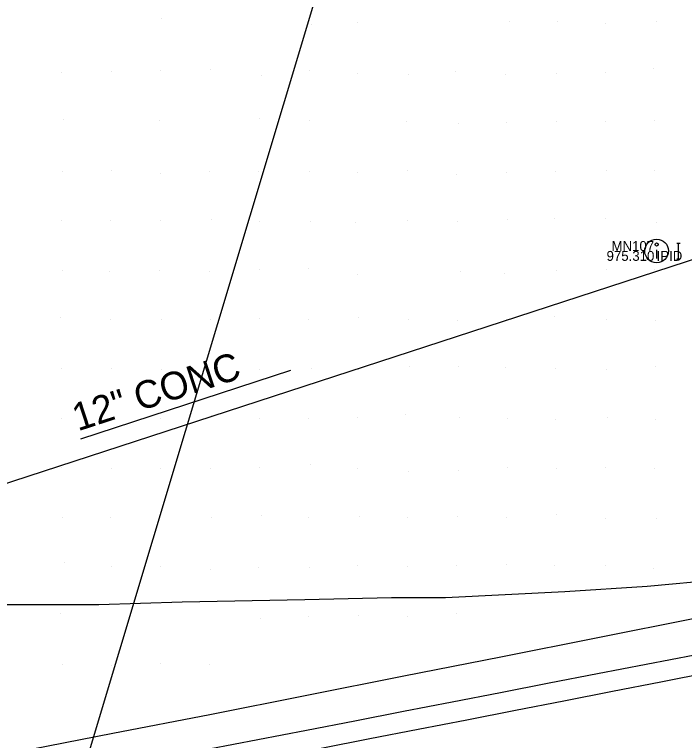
# Model space of a CAD drawing. Extents: x 2262025 to 2264532, y 740981 to 742724.
# Drawn here: x 2263020.8 to 2263088.6, y 742043.1 to 742116.6 of the extents above; entities that cross this region are included whole.
import ezdxf

# ---------------------------------------------------------------- set-up
doc = ezdxf.new("R2010")
doc.units = 0
for name, color, linetype in [('DR_X_Storm_Sewer', 7, 'Continuous'), ('DR_X_Text', 7, 'Continuous'), ('GE_X_Alignment_1000_Curve_Data', 7, 'Continuous'), ('GE_X_Alignment_100_Cardinal_Points', 7, 'Continuous'), ('GE_X_Alignment_100_Curve_Data', 7, 'Continuous'), ('Ground Shots', 7, 'Continuous'), ('HY_X_Spring_Cells', 7, 'Continuous'), ('RW_X_CL', 7, 'Continuous'), ('RW_X_CL_1000_Distances', 7, 'Continuous'), ('SV_X_Text_Comment', 7, 'Continuous'), ('SV_X_Text_Elevation', 7, 'Continuous')]:
    doc.layers.add(name, color=color, linetype=linetype)

msp = doc.modelspace()

# ---------------------------------------------------------------- linework, layer by layer
at = {"layer": 'DR_X_Storm_Sewer'}
for p, q in [((2263148.873, 742443.512), (2262984.252, 741895.043)), ((2263148.873, 742443.512), (2262984.252, 741895.043)), ((2262955.205, 742048.032), (2263118.436, 742101.27))]:
    msp.add_line(p, q, dxfattribs=at)
at = {"layer": 'DR_X_Text'}
msp.add_line((2263048.755, 742080.542), (2263027.511, 742073.613), dxfattribs=at)
at = {"layer": 'GE_X_Alignment_1000_Curve_Data'}
msp.add_lwpolyline([(2263040.535, 742042.275), (2263045.444, 742043.228), (2263050.352, 742044.182), (2263055.26, 742045.135), (2263060.168, 742046.088), (2263065.077, 742047.041), (2263069.985, 742047.994), (2263074.893, 742048.947), (2263079.802, 742049.9), (2263084.71, 742050.853), (2263089.618, 742051.806)], dxfattribs=at)
at = {"layer": 'GE_X_Alignment_100_Cardinal_Points'}
msp.add_lwpolyline([(2263009.27, 742056.896), (2263029.372, 742056.896), (2263037.795, 742057.158), (2263050.186, 742057.378), (2263058.962, 742057.599), (2263064.408, 742057.599), (2263076.491, 742058.195), (2263084.803, 742058.746), (2263099.443, 742060.092), (2263108.285, 742061.151), (2263115.958, 742062.254), (2263129.143, 742064.35), (2263140.41, 742066.38), (2263153.243, 742069.027), (2263159.461, 742070.241)], dxfattribs=at)
at = {"layer": 'GE_X_Alignment_100_Curve_Data'}
msp.add_lwpolyline([(2263020.956, 742041.954), (2263030.773, 742043.857), (2263040.591, 742045.759), (2263050.4, 742047.704), (2263060.208, 742049.654), (2263070.016, 742051.604), (2263079.824, 742053.554), (2263089.632, 742055.504), (2263099.437, 742057.471), (2263109.235, 742059.471), (2263119.032, 742061.472), (2263128.831, 742063.468), (2263138.595, 742065.612), (2263148.411, 742067.469), (2263158.09, 742069.913), (2263167.942, 742071.492), (2263177.746, 742073.459), (2263187.567, 742075.344), (2263197.385, 742077.239), (2263207.198, 742079.166), (2263217.01, 742081.093), (2263226.822, 742083.024), (2263236.633, 742084.961)], dxfattribs=at)
at = {"layer": 'Ground Shots'}
for p, q in [((2263035.649, 742116.116), (2263035.649, 742116.116)), ((2263050.869, 742115.572), (2263050.869, 742115.572)), ((2263055.569, 742115.764), (2263055.569, 742115.764)), ((2263070.887, 742115.817), (2263070.887, 742115.817)), ((2263075.773, 742115.86), (2263075.773, 742115.86)), ((2263080.613, 742115.663), (2263080.613, 742115.663)), ((2263085.782, 742115.871), (2263085.782, 742115.871)), ((2263025.591, 742110.658), (2263025.591, 742110.658)), ((2263030.687, 742110.796), (2263030.687, 742110.796)), ((2263035.604, 742110.941), (2263035.604, 742110.941)), ((2263040.656, 742111.047), (2263040.656, 742111.047)), ((2263050.621, 742110.87), (2263050.621, 742110.87)), ((2263055.569, 742110.592), (2263055.569, 742110.592)), ((2263060.715, 742110.464), (2263060.715, 742110.464)), ((2263065.441, 742110.842), (2263065.441, 742110.842)), ((2263070.499, 742110.515), (2263070.499, 742110.515)), ((2263075.67, 742110.625), (2263075.67, 742110.625)), ((2263080.639, 742110.688), (2263080.639, 742110.688)), ((2263085.423, 742111.086), (2263085.423, 742111.086)), ((2263045.781, 742110.358), (2263045.781, 742110.358)), ((2263045.641, 742106.023), (2263045.641, 742106.023)), ((2263025.785, 742105.931), (2263025.785, 742105.931)), ((2263035.515, 742105.822), (2263035.515, 742105.822)), ((2263050.635, 742105.834), (2263050.635, 742105.834)), ((2263060.454, 742105.733), (2263060.454, 742105.733)), ((2263065.761, 742105.547), (2263065.761, 742105.547)), ((2263070.553, 742105.673), (2263070.553, 742105.673)), ((2263075.597, 742105.755), (2263075.597, 742105.755)), ((2263080.606, 742105.701), (2263080.606, 742105.701)), ((2263085.537, 742105.858), (2263085.537, 742105.858)), ((2263025.696, 742100.697), (2263025.696, 742100.697)), ((2263030.599, 742100.763), (2263030.599, 742100.763)), ((2263035.589, 742100.493), (2263035.589, 742100.493)), ((2263040.594, 742100.696), (2263040.594, 742100.696)), ((2263045.533, 742100.7), (2263045.533, 742100.7)), ((2263050.615, 742100.673), (2263050.615, 742100.673)), ((2263055.543, 742100.608), (2263055.543, 742100.608)), ((2263060.573, 742100.758), (2263060.573, 742100.758)), ((2263065.545, 742100.42), (2263065.545, 742100.42)), ((2263070.63, 742100.543), (2263070.63, 742100.543)), ((2263075.511, 742100.671), (2263075.511, 742100.671)), ((2263080.722, 742100.777), (2263080.722, 742100.777)), ((2263085.58, 742100.83), (2263085.58, 742100.83)), ((2263030.58, 742095.745), (2263030.58, 742095.745)), ((2263040.777, 742095.822), (2263040.777, 742095.822)), ((2263060.553, 742095.764), (2263060.553, 742095.764)), ((2263070.643, 742095.843), (2263070.643, 742095.843)), ((2263075.447, 742095.896), (2263075.447, 742095.896)), ((2263080.601, 742095.918), (2263080.601, 742095.918)), ((2263025.63, 742095.695), (2263025.63, 742095.695)), ((2263035.624, 742095.682), (2263035.624, 742095.682)), ((2263045.623, 742095.611), (2263045.623, 742095.611)), ((2263050.757, 742095.613), (2263050.757, 742095.613)), ((2263055.33, 742095.509), (2263055.33, 742095.509)), ((2263065.659, 742095.584), (2263065.659, 742095.584)), ((2263085.78, 742095.526), (2263085.78, 742095.526)), ((2263025.67, 742090.645), (2263025.67, 742090.645)), ((2263035.483, 742090.665), (2263035.483, 742090.665)), ((2263045.638, 742090.775), (2263045.638, 742090.775)), ((2263050.516, 742090.919), (2263050.516, 742090.919)), ((2263075.647, 742090.63), (2263075.647, 742090.63)), ((2263080.707, 742090.753), (2263080.707, 742090.753)), ((2263085.571, 742090.739), (2263085.571, 742090.739)), ((2263030.461, 742090.57), (2263030.461, 742090.57)), ((2263040.599, 742090.584), (2263040.599, 742090.584)), ((2263055.498, 742090.292), (2263055.498, 742090.292)), ((2263065.927, 742090.585), (2263065.927, 742090.585)), ((2263070.419, 742090.401), (2263070.419, 742090.401)), ((2263025.526, 742085.948), (2263025.526, 742085.948)), ((2263030.543, 742085.761), (2263030.543, 742085.761)), ((2263035.688, 742085.748), (2263035.688, 742085.748)), ((2263040.648, 742085.735), (2263040.648, 742085.735)), ((2263045.579, 742085.822), (2263045.579, 742085.822)), ((2263050.611, 742085.748), (2263050.611, 742085.748)), ((2263055.649, 742085.887), (2263055.649, 742085.887)), ((2263060.638, 742085.693), (2263060.638, 742085.693)), ((2263065.588, 742085.643), (2263065.588, 742085.643)), ((2263070.601, 742085.699), (2263070.601, 742085.699)), ((2263075.451, 742085.973), (2263075.451, 742085.973)), ((2263080.668, 742085.735), (2263080.668, 742085.735)), ((2263085.658, 742085.574), (2263085.658, 742085.574)), ((2263025.628, 742080.73), (2263025.628, 742080.73)), ((2263030.634, 742080.713), (2263030.634, 742080.713)), ((2263035.656, 742080.7), (2263035.656, 742080.7)), ((2263040.597, 742080.685), (2263040.597, 742080.685)), ((2263045.656, 742080.662), (2263045.656, 742080.662)), ((2263050.853, 742080.751), (2263050.853, 742080.751)), ((2263055.651, 742080.695), (2263055.651, 742080.695)), ((2263060.765, 742080.93), (2263060.765, 742080.93)), ((2263065.733, 742080.914), (2263065.733, 742080.914)), ((2263070.442, 742080.837), (2263070.442, 742080.837)), ((2263075.548, 742080.755), (2263075.548, 742080.755)), ((2263080.691, 742080.683), (2263080.691, 742080.683)), ((2263085.637, 742080.919), (2263085.637, 742080.919)), ((2263040.734, 742076.042), (2263040.734, 742076.042)), ((2263060.323, 742076.08), (2263060.323, 742076.08)), ((2263025.621, 742075.734), (2263025.621, 742075.734)), ((2263030.629, 742075.692), (2263030.629, 742075.692)), ((2263035.611, 742075.692), (2263035.611, 742075.692)), ((2263045.616, 742075.681), (2263045.616, 742075.681)), ((2263050.595, 742075.713), (2263050.595, 742075.713)), ((2263055.489, 742075.784), (2263055.489, 742075.784)), ((2263065.788, 742075.765), (2263065.788, 742075.765)), ((2263070.651, 742075.732), (2263070.651, 742075.732)), ((2263075.57, 742075.641), (2263075.57, 742075.641)), ((2263080.801, 742075.76), (2263080.801, 742075.76)), ((2263085.61, 742075.606), (2263085.61, 742075.606)), ((2263050.787, 742071.016), (2263050.787, 742071.016)), ((2263025.621, 742070.722), (2263025.621, 742070.722)), ((2263030.597, 742070.682), (2263030.597, 742070.682)), ((2263035.64, 742070.672), (2263035.64, 742070.672)), ((2263040.62, 742070.654), (2263040.62, 742070.654)), ((2263045.637, 742070.717), (2263045.637, 742070.717)), ((2263055.57, 742070.691), (2263055.57, 742070.691)), ((2263060.706, 742070.37), (2263060.706, 742070.37)), ((2263065.777, 742070.422), (2263065.777, 742070.422)), ((2263070.661, 742070.705), (2263070.661, 742070.705)), ((2263075.667, 742070.647), (2263075.667, 742070.647)), ((2263080.62, 742070.7), (2263080.62, 742070.7)), ((2263085.551, 742070.637), (2263085.551, 742070.637)), ((2263025.669, 742065.694), (2263025.669, 742065.694)), ((2263030.521, 742065.663), (2263030.521, 742065.663)), ((2263035.573, 742065.733), (2263035.573, 742065.733)), ((2263040.712, 742065.734), (2263040.712, 742065.734)), ((2263045.804, 742065.887), (2263045.804, 742065.887)), ((2263050.583, 742065.712), (2263050.583, 742065.712)), ((2263055.704, 742065.754), (2263055.704, 742065.754)), ((2263060.537, 742065.719), (2263060.537, 742065.719)), ((2263065.658, 742065.75), (2263065.658, 742065.75)), ((2263070.629, 742065.694), (2263070.629, 742065.694)), ((2263075.63, 742065.959), (2263075.63, 742065.959)), ((2263080.59, 742065.543), (2263080.59, 742065.543)), ((2263085.73, 742065.61), (2263085.73, 742065.61)), ((2263025.852, 742061.13), (2263025.852, 742061.13)), ((2263030.614, 742060.679), (2263030.614, 742060.679)), ((2263035.641, 742060.689), (2263035.641, 742060.689)), ((2263045.459, 742060.623), (2263045.459, 742060.623)), ((2263050.709, 742060.666), (2263050.709, 742060.666)), ((2263055.563, 742060.802), (2263055.563, 742060.802)), ((2263060.543, 742060.757), (2263060.543, 742060.757)), ((2263065.497, 742060.789), (2263065.497, 742060.789)), ((2263070.587, 742060.93), (2263070.587, 742060.93)), ((2263075.454, 742060.839), (2263075.454, 742060.839)), ((2263080.635, 742060.816), (2263080.635, 742060.816)), ((2263085.47, 742060.558), (2263085.47, 742060.558)), ((2263040.682, 742060.405), (2263040.682, 742060.405)), ((2263025.523, 742055.968), (2263025.523, 742055.968)), ((2263045.669, 742055.466), (2263045.669, 742055.466)), ((2263050.584, 742055.623), (2263050.584, 742055.623)), ((2263055.617, 742055.801), (2263055.617, 742055.801)), ((2263060.593, 742055.698), (2263060.593, 742055.698)), ((2263065.483, 742056.015), (2263065.483, 742056.015)), ((2263035.597, 742050.946), (2263035.597, 742050.946)), ((2263025.721, 742050.847), (2263025.721, 742050.847)), ((2263030.653, 742050.732), (2263030.653, 742050.732)), ((2263040.552, 742050.865), (2263040.552, 742050.865))]:
    msp.add_line(p, q, dxfattribs=at)
at = {"layer": 'RW_X_CL_1000_Distances'}
msp.add_lwpolyline([(2263051.852, 742042.368), (2263056.76, 742043.322), (2263061.668, 742044.275), (2263066.576, 742045.229), (2263071.484, 742046.183), (2263076.391, 742047.144), (2263081.298, 742048.105), (2263086.205, 742049.066), (2263091.111, 742050.028), (2263096.018, 742050.989), (2263100.925, 742051.95), (2263105.832, 742052.911), (2263110.738, 742053.872), (2263115.646, 742054.828), (2263120.554, 742055.785), (2263125.462, 742056.737), (2263130.371, 742057.689), (2263135.279, 742058.641), (2263140.188, 742059.593), (2263145.096, 742060.545), (2263150.005, 742061.498), (2263154.913, 742062.45), (2263159.822, 742063.402)], dxfattribs=at)
at = {"layer": 'SV_X_Text_Elevation'}
msp.add_line((2263085.767, 742092.764), (2263085.767, 742091.88), dxfattribs=at)
for points in [[(2263087.797, 742093.447), (2263088.15, 742093.447)], [(2263087.974, 742091.847), (2263087.974, 742093.447)], [(2263087.797, 742091.847), (2263088.15, 742091.847)]]:
    msp.add_lwpolyline(points, dxfattribs=at)
for centre, radius in [((2263085.767, 742092.647), 1.2), ((2263085.767, 742093.299), 0.16)]:
    msp.add_circle(centre, radius, dxfattribs=at)

# ---------------------------------------------------------------- texts
at = {"layer": 'DR_X_Text'}
msp.add_text('12" CONC', height=2.8, rotation=18.0638, dxfattribs=at).set_placement((2263027.239, 742074.391))
at = {"layer": 'HY_X_Spring_Cells'}
msp.add_text('975.310', height=1, dxfattribs=at).set_placement((2263080.706, 742091.647))
at = {"layer": 'RW_X_CL'}
msp.add_text('IPID', height=1, dxfattribs=at).set_placement((2263085.767, 742091.647))
at = {"layer": 'SV_X_Text_Comment'}
msp.add_text('MN107', height=1, dxfattribs=at).set_placement((2263081.209, 742092.647))

doc.saveas('drawing.dxf')
